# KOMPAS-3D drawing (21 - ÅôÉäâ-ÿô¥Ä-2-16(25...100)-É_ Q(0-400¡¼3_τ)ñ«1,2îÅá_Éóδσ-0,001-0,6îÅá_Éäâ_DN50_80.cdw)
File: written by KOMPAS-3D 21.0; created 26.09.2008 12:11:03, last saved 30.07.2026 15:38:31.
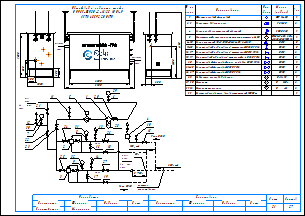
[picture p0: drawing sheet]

Sheets 1-2: A3, landscape

Document properties: Наименование: Макро:21; Автор: RaskoAdmin; Форматы листов документа: 2xA3; Полное имя файла: \\ur38nt01\Departments\КТО\КБ ПУРДГ\Заявки\Прайс-лист на типовые шкафы ГРПШ\ПУРДГ_стандарт_30_04_2026\ПУРДГ с РДГ(Н, В)\ПУРДГ-ШУЭО-2-16(25...100)-Р_ Q(0-400нм3_ч)до1,2МПа_Рвых-0,001-0,6МПа_РДГ_DN50_80.cdw

Title block, sheet 1: Наименование: Пункт учета газа / ПУГ-Ш-400-Р / ЛГТИ.485922.001ТУ; designation: ЛГТИ.03.4411141; sheet number: 1; Количество листов документа: 2; organisation: ООО "ЭЛЬСТЕР Газэлектроника"; Форматы листов документа: A3; stored path: C:\Рабочие документы\Компас\ПУГ\Схема.cdw; Разработал: Устинов; Проверил: Кошкин; Утвердил: Кошкин
Title block, sheet 2: sheet number: 2; stored path: D:\Рабочие документы\Заявки\ПУРДГ\ПУРДГ-ШУЭО-2-100-Р 4411220.cdw; designation, second copy: ЛГТИ.03.4411141-

Views: Вид 1, Вид 2
Referenced files: wcvoit.frw
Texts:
  Normal
  № на
  схеме
  Усл.
  обозн.
  Марка
  (модель)
  Кол.
  Фильтр газовый фланцевый
  ФГ 16-50
  Регулятор давления газа
  РДГ-50
  Клапан предохранительный сбросной
  КПС DN20
  Измерительный комплекс с ротационным счетчиком Ду50
  СГ-ЭК-Р-(0,2...2,0)-
  Кран кнопочный VE-РАСКО-НЗ-1,6-G1/2-М20
  DN15
  Кран шаровой "под приварку" штуцерный DN20 PN16
  DN20
  Кран шаровой "под приварку" штуцерный DN15 PN16
  Кран шаровой "под приварку" штуцерный п/п DN20 PN16
  Кран шаровой фланцевый с мех. приводом DN50 PN16
  Кран шаровой фланцевый DN50 PN16
  Кран шаровой фланцевый DN80 PN16
  DN50
  DN80
  Индикатор перепада давления
  Манометр
  Манометр-напоромер
  Электрообогреватель взрывозащищенный 1000Вт
  Delta 15
  0...     МПа
  0...     кПа
  Общий вид и габариты шкафа
  ПУРДГ-ШУЭО-2-16(25...100)-Р
  Выход газа
  Вход газа
  logo-rasko-ge.png
  DN 1
  местное
  сопротивление
  Римп DN20
  Выход
  газа
  Р=     кПа
  Вход
  Р=       МПа
  PDI
  Должность
  Конструктор
  Фамилия
  Подпись
  Дата
  Согласовано
  Максимкин
  Лист
  Листов
  POLYLINE_STYLE_0.18_RGB_0_0_0
  POLYLINE_STYLE_0.50_RGB_0_0_0
  POLYLINE_STYLE_0.34_RGB_0_0_0
  PHANTOM_RGB_0_0_0_SC_1_THICK_0.18
  K5LT_THIN_RGB_0_0_0_THICK_0.18
  K5LT32769_RGB_0_0_0_THICK_0.18
  K5LT12_RGB_0_0_0_SC_1_THICK_0.18
  K5LT_DASHED_RGB_0_0_0_SC_1_THICK_0.18
  ACISOTGL_RGB_0_0_0_SC_0.8_THICK_0.25
  CONTINUOUS_RGB_0_127_31_THICK_0.3
  CONTINUOUS_RGB_0_0_255_THICK_0.35
  CONTINUOUS_RGB_255_0_0_THICK_0.35
  POLYLINE_STYLE_0.25_RGB_0_0_0
  CONTINUOUS_RGB_0_0_0_THICK_0.5
  POLYLINE_STYLE_0.35_RGB_0_0_255
  CONTINUOUS_RGB_0_0_0_THICK_0.4
  CONTINUOUS_RGB_0_0_0_THICK_0.35
  НЕВИДИМАЯ_RGB_0_0_0_SC_0.3_THICK_0.25
  СONTINUOUS_RGB_0_0_0_THICK_0.25
  ОСЕВАЯ2_RGB_248_153_30_SC_0.3_THICK_0.25
  Без оформления
Dimensions and other numbers on the sheet: 1; 2, 3; 2; 4; 5; 6-10; 11-15; 16, 17; 18, 19; 20; 21-25; 26, 27; 28; 29, 30; 31, 32; 33; 1500; 250; 300; 1050; 550; 305; 2800; 4130; 2000; 3100; 5,,,7DN 1; 7; 30; 12; 21; 22; 23; 11; 6; 29; 24; 31; 8; 13; 26; 18; 10; 15; 25; 32; 9; 3; 14; 27; 19; 16; 17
